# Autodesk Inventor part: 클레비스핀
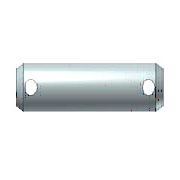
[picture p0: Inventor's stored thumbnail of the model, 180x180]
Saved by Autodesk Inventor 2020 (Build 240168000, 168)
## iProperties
Created: 2012-02
Part Number: 클레비스핀
Material: 강철
Description: 머리가 없는 클레비스 핀 B
Document SubType Name: Modeling
Standard: ISO 2340
Designer: mduedu
Standard Revision: Second edition 1986-11-01
Standards Organization: ISO
Language: ko-KR
Size Designation: B - 8 x 45
Categories: <MemberInstance><Categories><Category DisplayName="조임쇠" InternalName="e4da775c-781d-43d5-af7c-5136215cf5a6" Mnemonic="FSTN"><Category DisplayName="핀" InternalNa
Density: 7.85 g/cm^3
Appearance: 반광택
IsCustomPart: 1
Author: mduedu
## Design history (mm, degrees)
sketch "스케치1"
  geometry: L1 (-4.5, 0)-(-4.5, 4); L2 (-4.5, 4)-(35.5, 4); L3 (35.5, 4)-(35.5, 0); L4 (-4.5, 0)-(35.5, 0); L5 (0, -2)-(0, 5) reference; L6 (-13.5, 0)-(49.5, 0) reference; C1 r 1 at (-1, 0); C2 r 1 at (32, 0)
  constraints: 8 end point, 2 centre point, 2 perpendicular, 2 point on line, 1 collinear, 1 parallel, 1 tangent, 1 vertical
  dimensions: "d0" = 8 diameter of L2 L4 (= NND); "d1" = 40 distance of L1.end L2.end (= NLG); "d2" = 3.5 distance from line of L1 C1.centre (= DIST1); "d3" = 3.5 distance from line of L3 C2.centre (= DIST2); "d4" = 2 diameter of C1 (= BOR1); "d5" = 2 diameter of C2 (= BOR2)
revolve "본체" stored, may be unused: angle "d7" = 90 deg
extrude "구멍1" cut sketch "스케치1" extent not by distance; taper "d6" = 0 deg; stored distance "d8" = 10
extrude "구멍2" cut sketch "스케치1" extent not by distance; taper "d13" = 0 deg; stored distance "d14" = 10
workaxis "Work Axis1"
workaxis "Work Axis2"
workplane "Work Plane1"
node "작업 평면5"
body "Solid1"
chamfer "모따기2" distance "d9" = 2 (= PHH2); stored, may be unused: angle "d10" = 30 deg (= FAWI2), second distance "d40" = 2 (= PHH2)
chamfer "모따기1" distance "d11" = 2 (= PHH1); stored, may be unused: angle "d12" = 30 deg (= FAWI1), second distance "d41" = 2 (= PHH1)
other parameters: "NLG" = 40 [user parameter; used in 1 equation term], "NND" = 8 [user parameter; used in 1 equation term], "PHH1" = 2 [user parameter; used in 3 equation terms], "PHH2" = 2 (= PHH1) [user parameter; used in 2 equation terms], "FAWI1" = 30 deg [user parameter; used in 1 equation term], "FAWI2" = 30 deg [user parameter; used in 1 equation term], "DIST1" = 3.5 [user parameter; used in 4 equation terms], "DIST2" = 3.5 (= DIST1) [user parameter; used in 1 equation term], "BOR1" = 2 [user parameter; used in 4 equation terms], "BOR2" = 2 (= BOR1) [user parameter; used in 1 equation term], "d15" = 0, "d42" = 0, "d43" = 0, "d44" = -4.5 (= -0.5 x BOR1 - DIST1), "d45" = -4.5 (= -0.5 x BOR1 - DIST1), "d47" = 0, "d48" = 0, "d49" = 0, "d50" = 0, "d51" = 0, "d52" = 0
